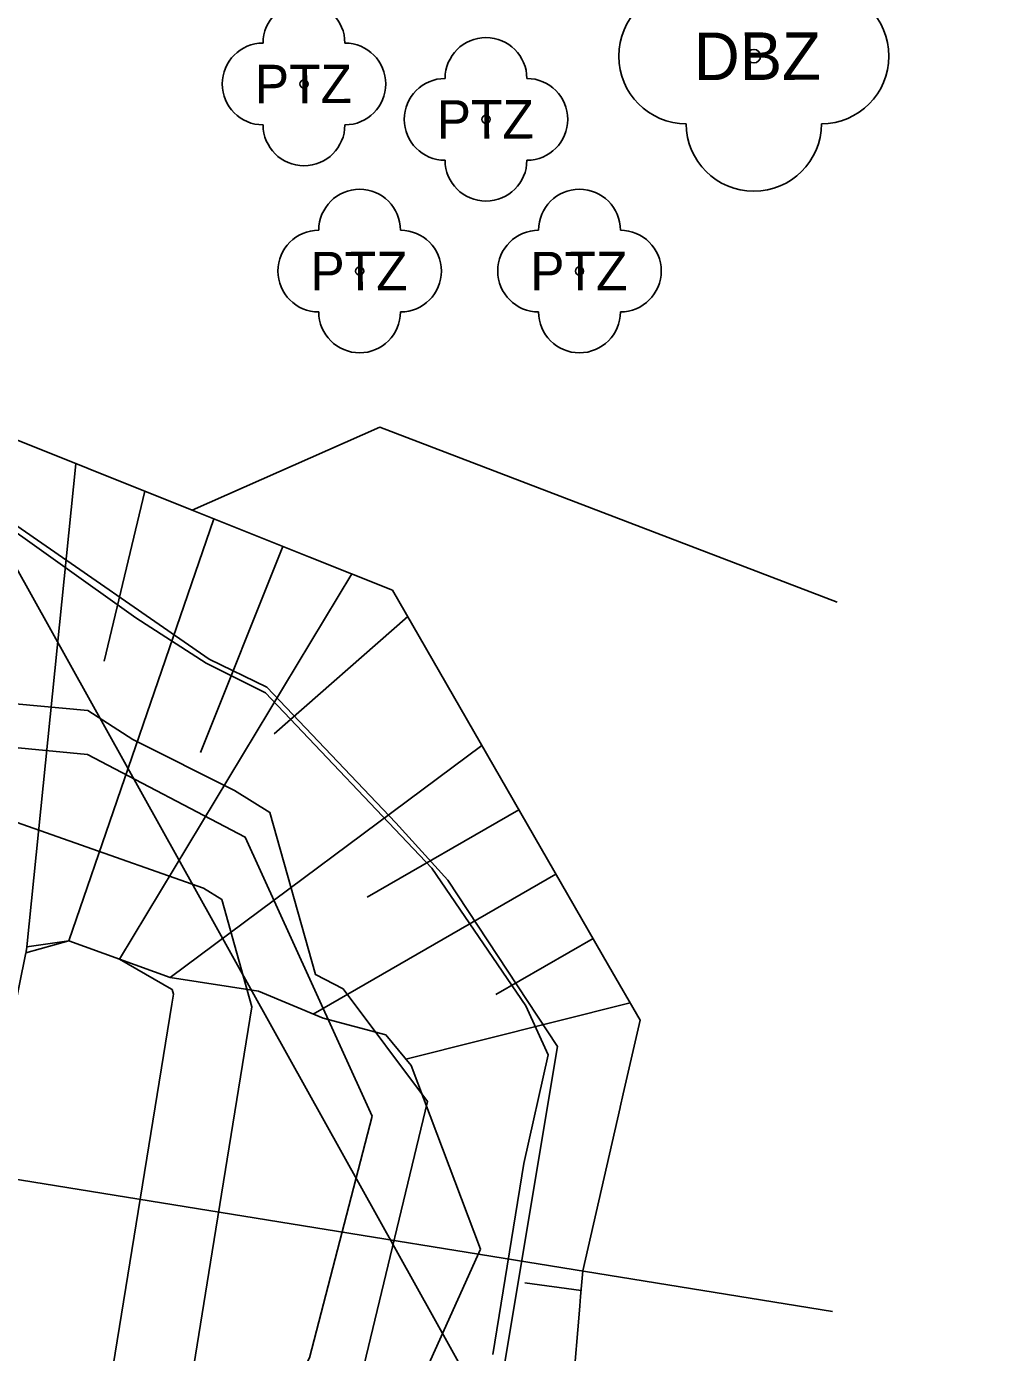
# Model space of a CAD drawing. Extents: x -564037 to -563722, y -1163561 to -1163412.
# Drawn here: x -563920.35 to -563903.91, y -1163487.66 to -1163465.35 of the extents above; entities that cross this region are included whole.
import ezdxf

# ---------------------------------------------------------------- set-up
doc = ezdxf.new("R2010")
doc.units = 0
for name, color, linetype in [('5', 7, 'Continuous'), ('Default', 7, 'Continuous'), ('Line', 7, 'Continuous'), ('Vrstva 1', 7, 'Continuous'), ('Vrstva 2', 7, 'Continuous')]:
    doc.layers.add(name, color=color, linetype=linetype)

msp = doc.modelspace()

# ---------------------------------------------------------------- linework, layer by layer
for points in [[(-563930.469, -1163501.126), (-563927.863, -1163499.14), (-563925.937, -1163497.674), (-563921.059, -1163495.43), (-563912.613, -1163489.681), (-563911.421, -1163482.517), (-563913.266, -1163479.715), (-563914.137, -1163478.749), (-563916.309, -1163476.467), (-563917.281, -1163475.995), (-563923.761, -1163471.506), (-563924, -1163472.797), (-563925.435, -1163477.844), (-563927.008, -1163483.992), (-563927.659, -1163487.507), (-563928.13, -1163490.05), (-563928.806, -1163493.379), (-563930.34, -1163499.841), (-563930.622, -1163501.15)], [(-563915.586, -1163481.384), (-563914.537, -1163483.686), (-563915.595, -1163487.753), (-563917.092, -1163490.681), (-563919.984, -1163492.255), (-563925.31, -1163491.764), (-563926.027, -1163491.364), (-563926.218, -1163490.597), (-563925.375, -1163485.285), (-563924.678, -1163482.734), (-563924.029, -1163478.524), (-563922.899, -1163477.259), (-563919.326, -1163477.602), (-563916.674, -1163478.991)]]:
    msp.add_lwpolyline(points, close=True)
for points in [[(-563912.506, -1163487.699), (-563911.986, -1163484.484), (-563911.574, -1163482.655), (-563911.953, -1163481.832), (-563913.535, -1163479.514), (-563916.332, -1163476.565), (-563917.329, -1163476.066), (-563918.514, -1163475.302), (-563923.696, -1163471.61)], [(-563906.71, -1163475.04), (-563914.411, -1163472.092), (-563917.567, -1163473.488)], [(-563914.71, -1163488.029), (-563913.607, -1163483.439), (-563913.607, -1163483.439), (-563915.027, -1163481.543), (-563915.494, -1163481.306), (-563916.26, -1163478.576), (-563916.853, -1163478.206), (-563918.564, -1163477.348), (-563919.324, -1163476.858), (-563923.345, -1163476.489), (-563923.394, -1163476.556), (-563923.434, -1163476.636), (-563923.448, -1163476.663), (-563923.45, -1163476.666), (-563923.468, -1163476.663)], [(-563921.906, -1163478.258), (-563917.376, -1163479.852), (-563917.069, -1163480.044), (-563916.563, -1163481.846), (-563917.23, -1163485.969), (-563917.681, -1163488.756)], [(-563921.157, -1163485.676), (-563920.712, -1163482.662), (-563920.712, -1163482.662), (-563920.712, -1163482.662), (-563920.712, -1163482.662), (-563920.364, -1163480.938), (-563919.644, -1163480.737), (-563917.94, -1163481.353), (-563917.94, -1163481.353), (-563916.452, -1163481.582), (-563915.363, -1163482.04), (-563914.308, -1163482.319), (-563913.884, -1163482.835), (-563912.713, -1163485.924)], [(-563920.362, -1163480.924), (-563920.353, -1163480.87), (-563920.353, -1163480.865), (-563920.352, -1163480.86), (-563920.351, -1163480.854), (-563920.35, -1163480.849), (-563920.349, -1163480.846), (-563920.349, -1163480.843), (-563920.348, -1163480.836), (-563919.644, -1163480.737), (-563918.792, -1163481.045), (-563917.917, -1163481.551), (-563917.904, -1163481.558), (-563917.884, -1163481.632), (-563917.911, -1163481.802), (-563919.001, -1163488.543)], [(-563921.157, -1163485.676), (-563921.598, -1163488.562), (-563921.461, -1163489.159), (-563920.716, -1163489.381), (-563919.058, -1163489.245), (-563919.058, -1163489.245), (-563919.058, -1163489.245), (-563916.75, -1163488.907), (-563916.212, -1163488.994), (-563914.24, -1163489.313), (-563912.713, -1163485.924)]]:
    msp.add_lwpolyline(points)
at = {"layer": '5'}
for p, q in [((-563921.324, -1163473.035), (-563903.913, -1163504.291)), ((-563939.818, -1163481.63), (-563906.789, -1163486.973))]:
    msp.add_line(p, q, dxfattribs=at)
at = {"layer": 'Default'}
msp.add_lwpolyline([(-563911.245, -1163489.265), (-563911.055, -1163487.019), (-563911.044, -1163486.882), (-563911.03, -1163486.723), (-563910.994, -1163486.292), (-563910.364, -1163483.544), (-563910.362, -1163483.535), (-563910.311, -1163483.311), (-563910.027, -1163482.072), (-563910.558, -1163481.15), (-563914.197, -1163474.834), (-563915.601, -1163474.273), (-563917.567, -1163473.488), (-563921.074, -1163472.087)], dxfattribs=at)
at = {"layer": 'Line'}
for p, q in [((-563919.523, -1163472.707), (-563920.348, -1163480.836)), ((-563919.049, -1163476.03), (-563918.362, -1163473.17)), ((-563917.201, -1163473.634), (-563919.644, -1163480.737)), ((-563917.427, -1163477.568), (-563916.04, -1163474.098)), ((-563914.88, -1163474.562), (-563918.792, -1163481.045)), ((-563916.187, -1163477.252), (-563913.94, -1163475.281)), ((-563917.94, -1163481.353), (-563912.692, -1163477.447)), ((-563912.068, -1163478.53), (-563914.62, -1163480)), ((-563915.532, -1163481.969), (-563911.444, -1163479.613)), ((-563910.82, -1163480.696), (-563912.456, -1163481.639)), ((-563913.971, -1163482.729), (-563910.196, -1163481.779)), ((-563911.967, -1163486.494), (-563911.022, -1163486.623))]:
    msp.add_line(p, q, dxfattribs=at)
at = {"layer": 'Vrstva 2'}
for centre, radius in [((-563908.114, -1163465.848), 0.114), ((-563915.685, -1163466.316), 0.0688), ((-563912.622, -1163466.912), 0.0688), ((-563914.749, -1163469.465), 0.0688), ((-563911.049, -1163469.465), 0.0688)]:
    msp.add_circle(centre, radius, dxfattribs=at)
for centre, radius, start, end in [((-563909.251, -1163465.848), 1.137, 90, 270), ((-563906.977, -1163465.848), 1.137, 270, 90), ((-563915.685, -1163465.628), 0.688, 0, 180), ((-563916.373, -1163466.316), 0.688, 90, 270), ((-563914.997, -1163466.316), 0.688, 270, 90), ((-563912.622, -1163466.224), 0.688, 0, 180), ((-563913.31, -1163466.912), 0.688, 90, 270), ((-563911.934, -1163466.912), 0.688, 270, 90), ((-563915.685, -1163467.004), 0.688, 180, 0), ((-563908.114, -1163466.985), 1.137, 180, 0), ((-563912.622, -1163467.6), 0.688, 180, 0), ((-563914.749, -1163468.777), 0.688, 0, 180), ((-563911.049, -1163468.777), 0.688, 0, 180), ((-563915.437, -1163469.465), 0.688, 90, 270), ((-563914.061, -1163469.465), 0.688, 270, 90), ((-563911.737, -1163469.465), 0.688, 90, 270), ((-563910.361, -1163469.465), 0.688, 270, 90), ((-563914.749, -1163470.153), 0.688, 180, 0), ((-563911.049, -1163470.153), 0.688, 180, 0)]:
    msp.add_arc(centre, radius, start, end, dxfattribs=at)

# ---------------------------------------------------------------- texts
at = {"layer": 'Vrstva 1'}
for s, height, p in [('DBZ', 0.8, (-563909.124, -1163466.251)), ('PTZ', 0.648, (-563916.513, -1163466.642)), ('PTZ', 0.648, (-563913.451, -1163467.238)), ('PTZ', 0.648, (-563915.577, -1163469.791)), ('PTZ', 0.648, (-563911.877, -1163469.791))]:
    msp.add_text(s, height=height, rotation=0.1546, dxfattribs=at).set_placement(p)

doc.saveas('drawing.dxf')
